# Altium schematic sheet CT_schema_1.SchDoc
size 419 x 258 mm
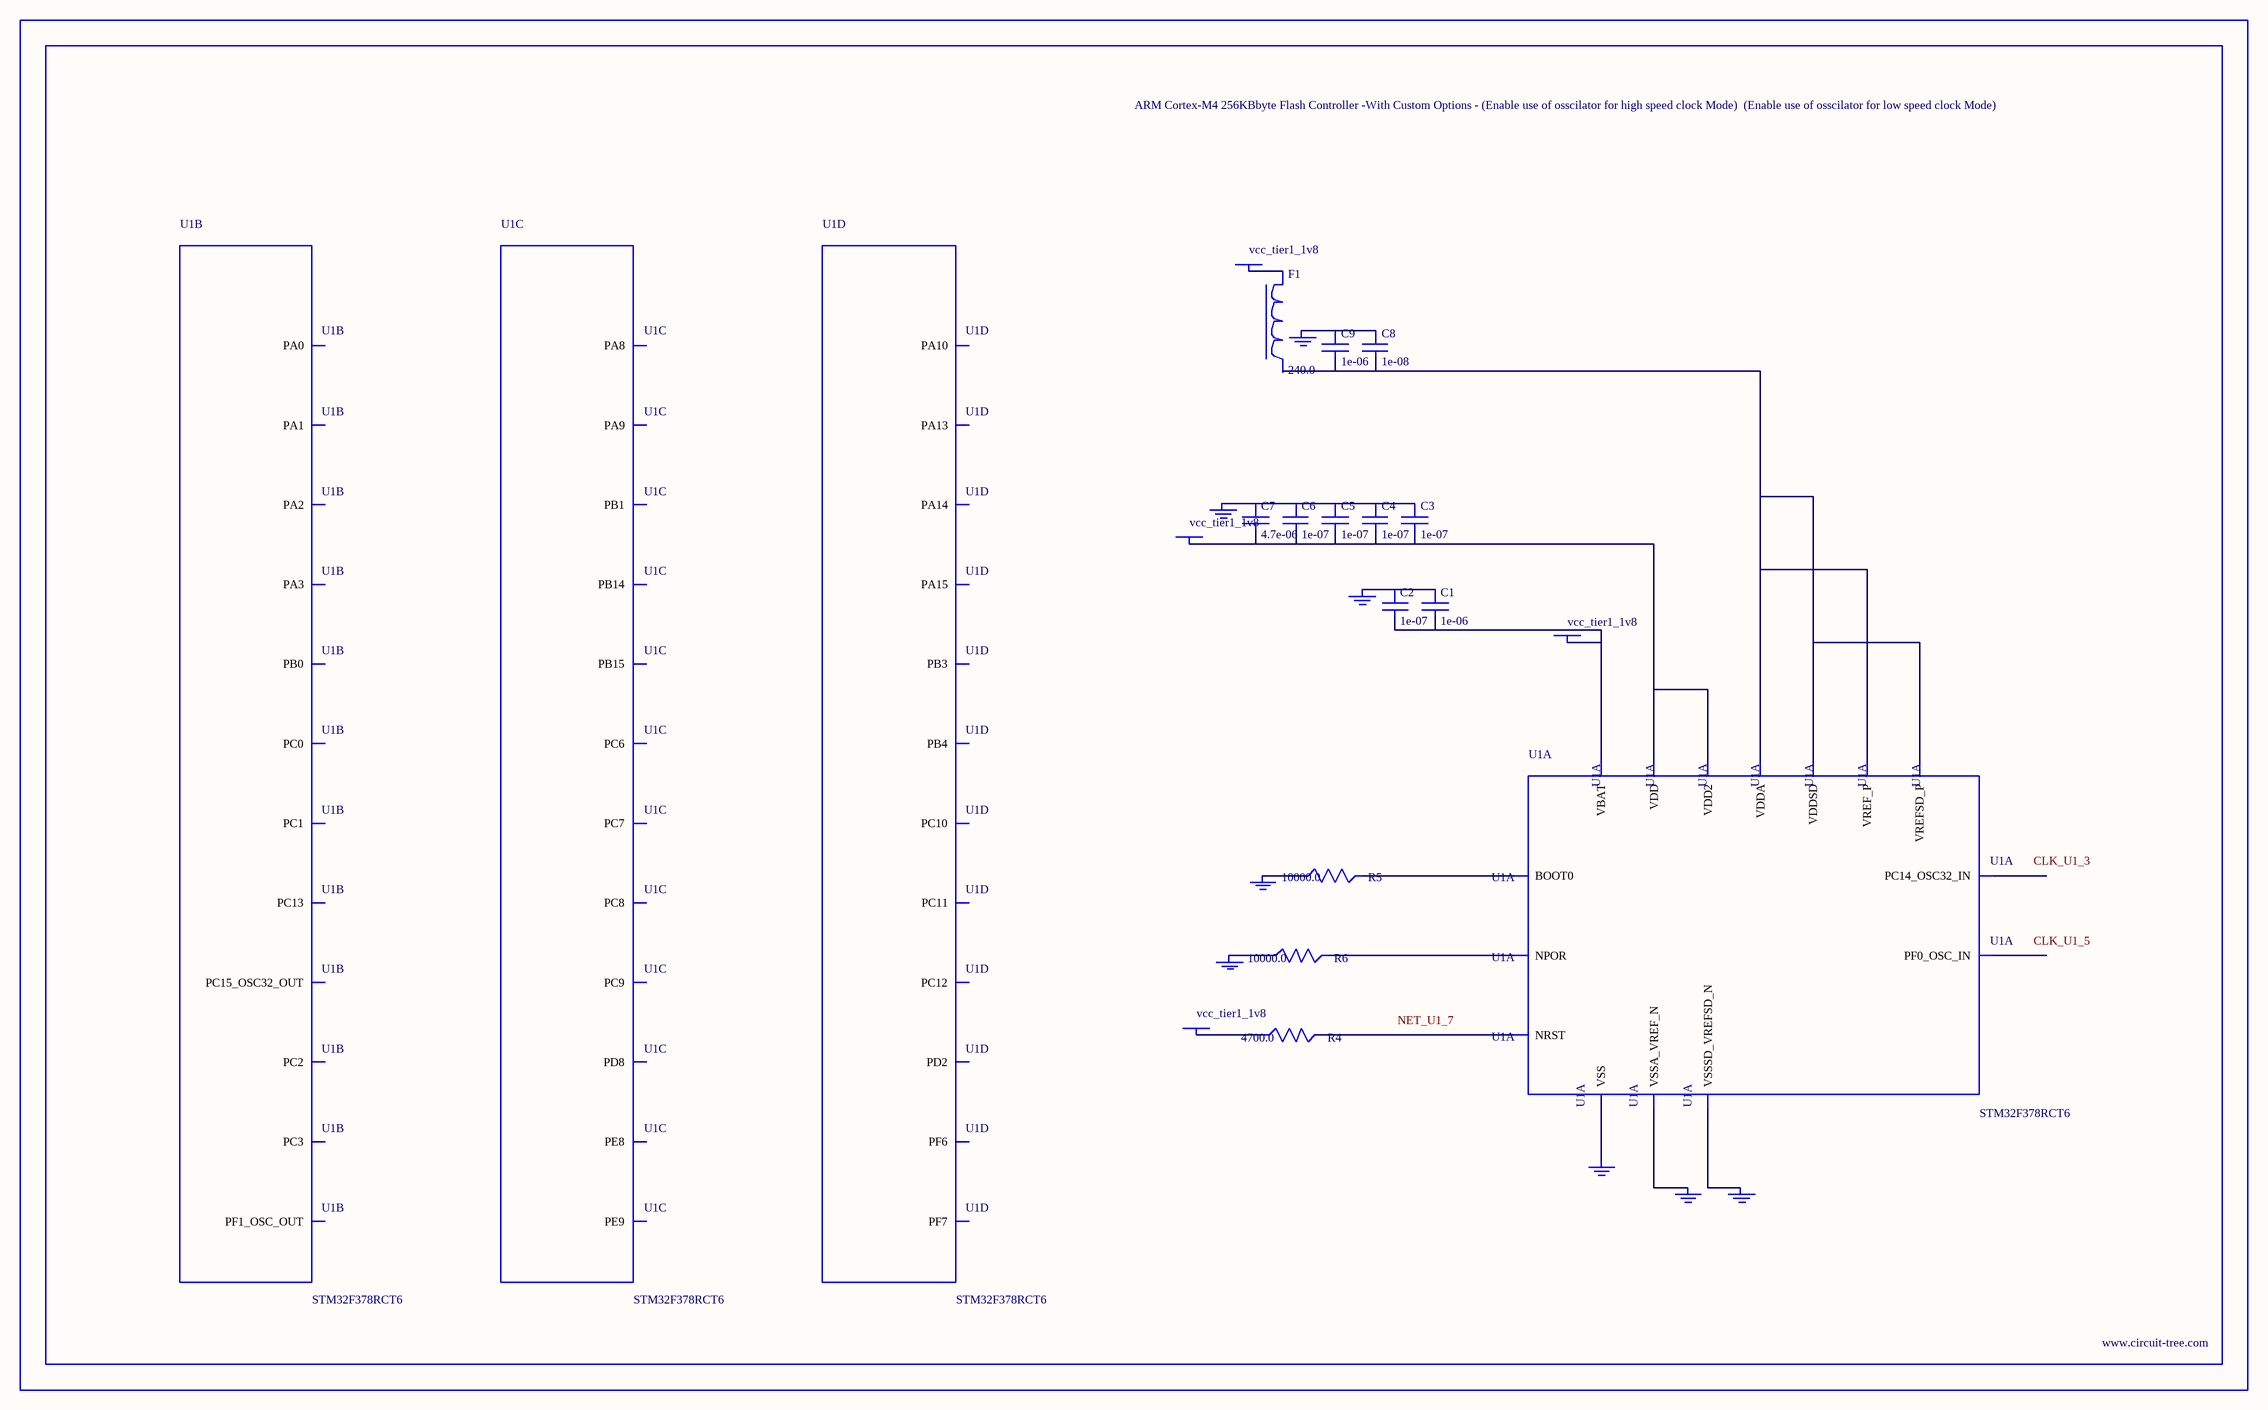
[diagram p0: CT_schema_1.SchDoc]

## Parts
BORDER0  (no value)
C1  1e-06  [C0603]
C2  1e-07  [C0603]
C3  1e-07  [C0603]
C4  1e-07  [C0603]
C5  1e-07  [C0603]
C6  1e-07  [C0603]
C7  4.7e-06  [C0603]
C8  1e-08  [C0603]
C9  1e-06  [C0603]
F1  240.0  [L0603]
GND_INSTANCE_0_0  (no value)
GND_INSTANCE_0_1  (no value)
GND_INSTANCE_0_2  (no value)
GND_INSTANCE_0_3  (no value)
GND_INSTANCE_0_4  (no value)
GND_INSTANCE_0_5  (no value)
GND_INSTANCE_0_6  (no value)
GND_INSTANCE_0_7  (no value)
POWER_INSTANCE_0_0  vcc_tier1_1v8
POWER_INSTANCE_0_1  vcc_tier1_1v8
POWER_INSTANCE_0_2  vcc_tier1_1v8
POWER_INSTANCE_0_3  vcc_tier1_1v8
R4  4700.0  [R0603]
R5  10000.0  [R0603]
R6  10000.0  [R0603]
U1  STM32F378RCT6  [LQFP64]  (parts A,B,C,D of 6)

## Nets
NetC1_1: C1.1 C2.1 GND_INSTANCE_0_0.0(GND)
NetC1_2: C1.2 C2.2 POWER_INSTANCE_0_0.0(PWR) U1.1(VBAT)
NetC3_1: C3.1 C4.1 C5.1 C6.1 C7.1 GND_INSTANCE_0_3.0(GND)
NetC3_2: C3.2 C4.2 C5.2 C6.2 C7.2 POWER_INSTANCE_0_2.0(PWR) U1.19(VDD) U1.64(VDD2)
NetC8_1: C8.1 C9.1 GND_INSTANCE_0_2.0(GND)
NetC8_2: C8.2 C9.2 U1.13(VDDA) U1.17(VREF_P) U1.32(VDDSD) U1.33(VREFSD_P)
NetF1_1: F1.1 POWER_INSTANCE_0_1.0(PWR)
NetGND_INSTANCE_0_1_0: GND_INSTANCE_0_1.0(GND) U1.12(VSSA_VREF_N)
NetGND_INSTANCE_0_4_0: GND_INSTANCE_0_4.0(GND) R6.1
NetGND_INSTANCE_0_5_0: GND_INSTANCE_0_5.0(GND) U1.31(VSSSD_VREFSD_N)
NetGND_INSTANCE_0_6_0: GND_INSTANCE_0_6.0(GND) R5.1
NetGND_INSTANCE_0_7_0: GND_INSTANCE_0_7.0(GND) U1.63(VSS)
NetPOWER_INSTANCE_0_3_0: POWER_INSTANCE_0_3.0(PWR) R4.1
NetR4_2: R4.2 U1.7(NRST)
NetR5_2: R5.2 U1.60(BOOT0)
NetR6_2: R6.2 U1.28(NPOR)

Not connected (* = marked no-connect by the designer): F1 2; U1 2(PC13) 3(PC14_OSC32_IN) 4(PC15_OSC32_OUT) 5(PF0_OSC_IN) 6(PF1_OSC_OUT) 8(PC0) 9(PC1) 10(PC2) 11(PC3) 14(PA0) 15(PA1) 16(PA2) 18(PA3) 26(PB0) 27(PB1) 29(PE8) 30(PE9) 34(PB14) 35(PB15) 36(PD8) 37(PC6) 38(PC7) 39(PC8) 40(PC9) 41(PA8) 42(PA9) 43(PA10) 46(PA13) 47(PF6) 48(PF7) 49(PA14) 50(PA15) 51(PC10) 52(PC11) 53(PC12) 54(PD2) 55(PB3) 56(PB4)

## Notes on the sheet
- Labels drawn without touching a wire or pin: CLK_U1_3, CLK_U1_5, NET_U1_7

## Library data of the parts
BORDER0 = BORDER_PAGE0
C1 C9 = C0603C105K3RACTU
C2-C6 = 06035C104K4Z2A
C7 = GRM188R6YA475KE15D
C8 = 06035C103K4Z2A
F1 = Z0603C241ASMST
GND_INSTANCE_0_0-GND_INSTANCE_0_7 = GND
POWER_INSTANCE_0_0-POWER_INSTANCE_0_3 = PWR
R4 = RC0603JR-074K7L
R5 R6 = RC0603JR-0710KL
